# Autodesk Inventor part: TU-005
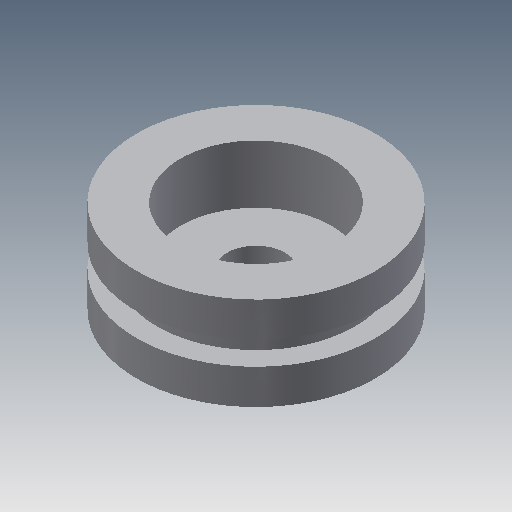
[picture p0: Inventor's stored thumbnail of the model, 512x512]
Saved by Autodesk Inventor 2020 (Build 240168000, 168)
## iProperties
Created: 2008-06
Part Number: TU-005
Document SubType Name: Modeling
Designer: PN
Density: 2.71 g/cm^3
Material: Aluminum-6061
Description: Piston
Mass: 37.1113 g
Surface Area: 62.8633 cm^2
Volume: 13.6942 cm^3
Appearance: Aluminum - Flat
Author: PN
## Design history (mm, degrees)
sketch "Sketch1"
  geometry: L1 (5, 0)-(5, 6); L2 (5, 6)-(13, 6); L3 (13, 6)-(13, 16); L4 (17, 10)-(17, 6); L5 (13, 16)-(20.5, 16); L6 (20.5, 16)-(20.5, 10); L7 (20.5, 10)-(17, 10); L8 (17, 6)-(20.5, 6); L9 (20.5, 6)-(20.5, 0); L10 (20.5, 0)-(5, 0); L11 (0, 0)-(0, 16)
  constraints: 22 end point, 2 collinear, 2 horizontal alignment, 1 horizontal, 1 perpendicular
  dimensions: "d0" = 10 diameter of L1 L11; "d1" = 26 diameter of L3 L11; "d2" = 34 diameter of L4 L11; "d3" = 41 diameter of L9 L11; "d4" = 6 distance between parallel lines of L8 L10; "d5" = 10 distance between parallel lines of L7 L10; "d6" = 16 distance between parallel lines of L5 L10
revolve "Revolution1" sketch "Sketch1" stored, may be unused: angle "d7" = 90 deg
body "Solid1"
